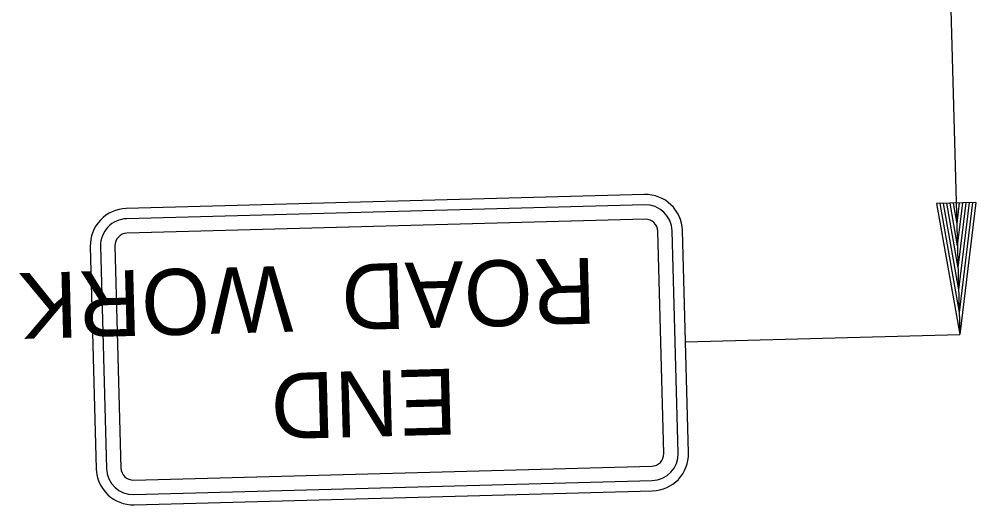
# Model space of a CAD drawing. Extents: x 1929653 to 1931621, y 596452 to 600944.
# Drawn here: x 1930715.8 to 1930803, y 600019.6 to 600063.8 of the extents above; entities that cross this region are included whole.
import ezdxf

# ---------------------------------------------------------------- set-up
doc = ezdxf.new("R2010")
doc.units = 0
doc.layers.add('P_TC_Signs_Temporary', color=7, linetype='Continuous')
doc.layers.add('R_Draft', color=7, linetype='Continuous')

msp = doc.modelspace()

# ---------------------------------------------------------------- linework, layer by layer
at = {"layer": 'P_TC_Signs_Temporary'}
for p, q in [((1930772.795, 600047.816), (1930725.562, 600046.548)), ((1930772.82, 600046.879), (1930725.587, 600045.611)), ((1930772.856, 600045.567), (1930725.623, 600044.299)), ((1930774.554, 600024.229), (1930774.01, 600044.472)), ((1930775.866, 600024.265), (1930775.322, 600044.507)), ((1930776.803, 600024.29), (1930776.26, 600044.533)), ((1930722.279, 600043.083), (1930722.822, 600022.841)), ((1930723.216, 600043.109), (1930723.76, 600022.866)), ((1930724.528, 600043.144), (1930725.072, 600022.901)), ((1930726.226, 600021.807), (1930773.459, 600023.075)), ((1930726.262, 600020.495), (1930773.495, 600021.763)), ((1930726.287, 600019.558), (1930773.52, 600020.825))]:
    msp.add_line(p, q, dxfattribs=at)
for centre, radius, start, end in [((1930772.886, 600044.442), 3.375, 1.53769, 91.53769), ((1930725.653, 600043.174), 3.375, 91.53769, 181.53769), ((1930772.886, 600044.442), 2.437, 1.53769, 91.53769), ((1930725.653, 600043.174), 2.437, 91.53769, 181.53769), ((1930772.886, 600044.442), 1.125, 1.53769, 91.53769), ((1930725.653, 600043.174), 1.125, 91.53769, 181.53769), ((1930773.429, 600024.199), 1.125, 271.53769, 1.53769), ((1930773.429, 600024.199), 2.437, 271.53769, 1.53769), ((1930773.429, 600024.199), 3.375, 271.53769, 1.53769), ((1930726.196, 600022.931), 3.375, 181.53769, 271.53769), ((1930726.196, 600022.931), 2.437, 181.53769, 271.53769), ((1930726.196, 600022.931), 1.125, 181.53769, 271.53769)]:
    msp.add_arc(centre, radius, start, end, dxfattribs=at)
at = {"layer": 'R_Draft'}
for p, q in [((1930798.241, 600157.41), (1930801.524, 600035.082)), ((1930802.998, 600047.095), (1930799.409, 600046.999)), ((1930799.409, 600046.999), (1930801.524, 600035.082)), ((1930799.708, 600047.007), (1930801.471, 600037.081)), ((1930800.011, 600047.015), (1930801.416, 600039.138)), ((1930800.31, 600047.023), (1930801.362, 600041.128)), ((1930800.619, 600047.031), (1930801.308, 600043.158)), ((1930800.922, 600047.039), (1930801.254, 600045.157)), ((1930801.484, 600047.055), (1930801.254, 600045.157)), ((1930801.783, 600047.063), (1930801.308, 600043.158)), ((1930802.096, 600047.071), (1930801.362, 600041.128)), ((1930802.395, 600047.079), (1930801.416, 600039.138)), ((1930802.699, 600047.087), (1930801.471, 600037.081)), ((1930802.998, 600047.095), (1930801.524, 600035.082)), ((1930776.531, 600034.411), (1930801.524, 600035.082))]:
    msp.add_line(p, q, dxfattribs=at)

# ---------------------------------------------------------------- texts
at = {"layer": 'P_TC_Signs_Temporary'}
for s, p in [('ROAD  WORK', (1930768.283, 600042.068)), ('END', (1930755.619, 600031.974))]:
    msp.add_text(s, height=6, rotation=181.53769, dxfattribs=at).set_placement(p)

doc.saveas('drawing.dxf')
